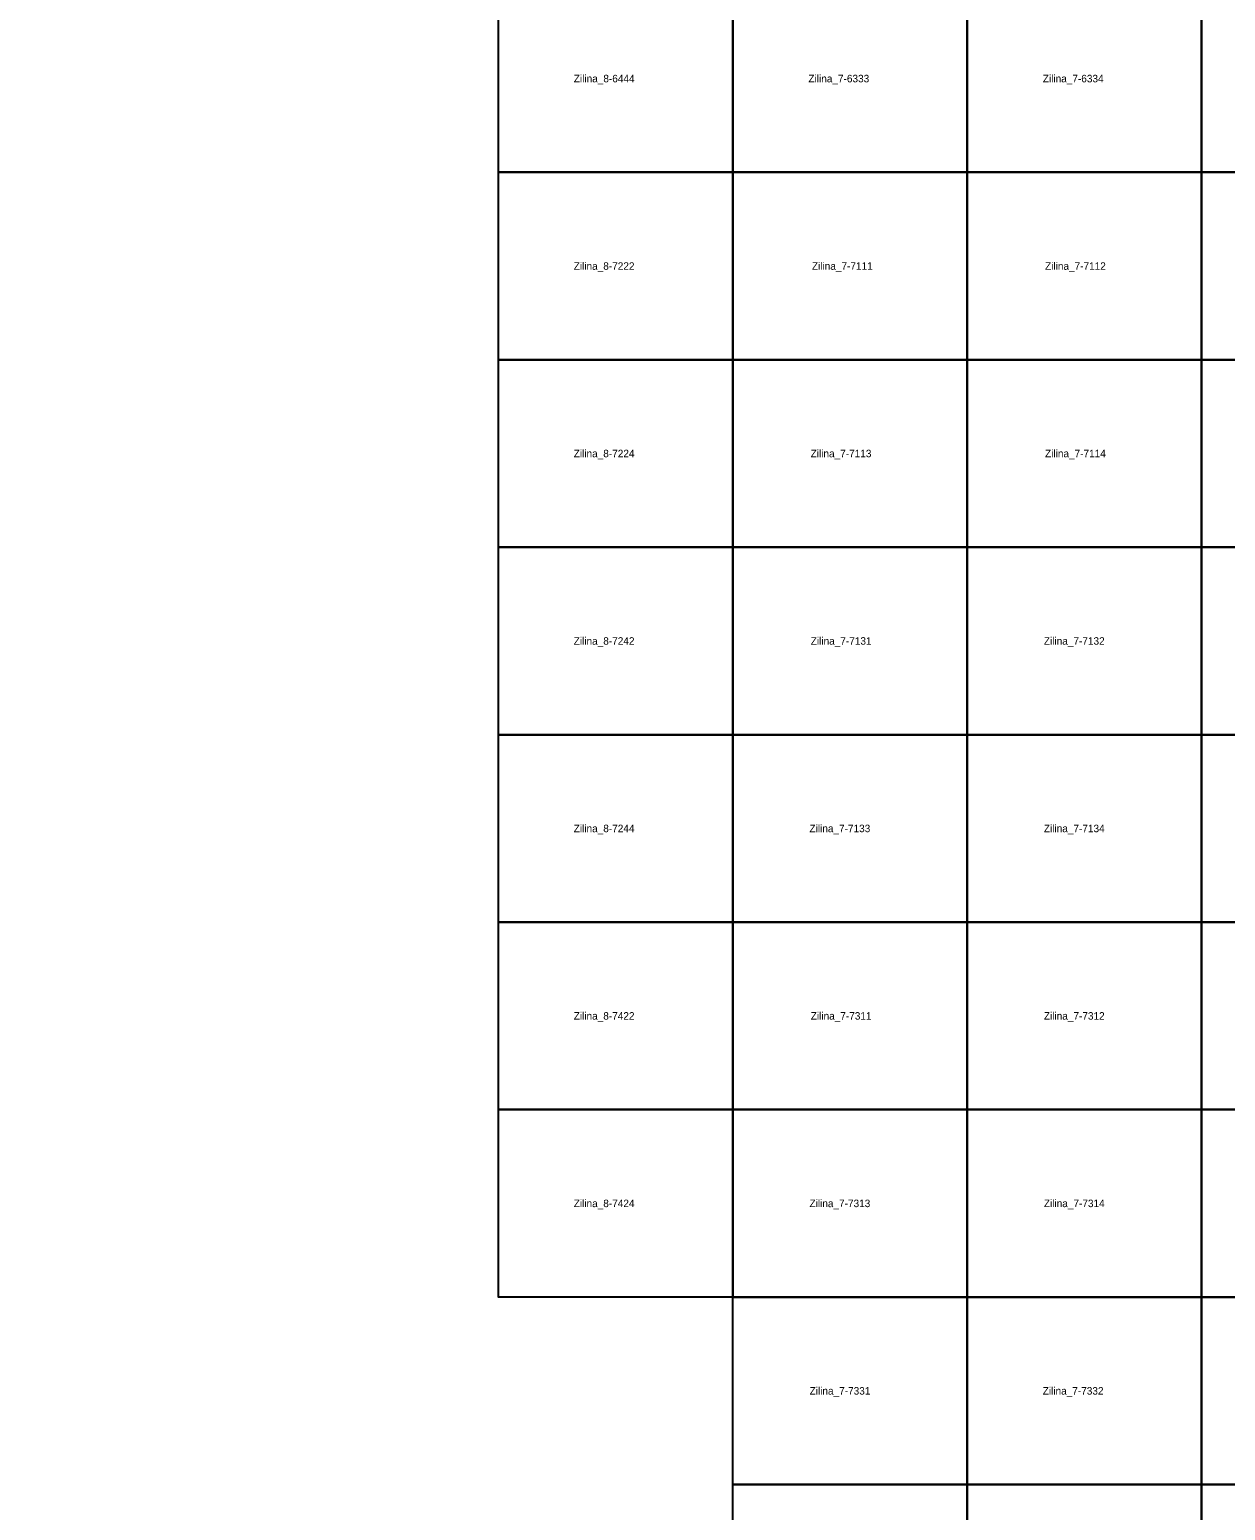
# Model space of a CAD drawing. Extents: x -445938 to -437812, y -1177250 to -1169500.
# Drawn here: x -445938 to -444343, y -1175784 to -1173810 of the extents above; entities that cross this region are included whole.
import ezdxf

# ---------------------------------------------------------------- set-up
doc = ezdxf.new("R2010")
doc.units = 0
for name, color, linetype in [('Vrstva 1', 7, 'Continuous'), ('Vrstva 4', 7, 'Continuous'), ('Vrstva 6', 7, 'Continuous')]:
    doc.layers.add(name, color=color, linetype=linetype)

msp = doc.modelspace()

# ---------------------------------------------------------------- linework, layer by layer
at = {"layer": 'Vrstva 1'}
msp.add_lwpolyline([(-440625, -1175500), (-441562.5, -1175500), (-441562.5, -1175000), (-442812.5, -1175000), (-442812.5, -1175750), (-443437.5, -1175750), (-443437.5, -1177250), (-445000, -1177250), (-445000, -1175500), (-445312.5, -1175500), (-445312.5, -1173750), (-445937.5, -1173750), (-445937.5, -1172250), (-445625, -1172250), (-445625, -1169500), (-444062.5, -1169500), (-444062.5, -1169750), (-441562.5, -1169750), (-441562.5, -1170000), (-440000, -1170000)], dxfattribs=at)
at = {"layer": 'Vrstva 4'}
for points in [[(-445000, -1173750), (-445000, -1174000), (-445312.5, -1174000), (-445312.5, -1173750)], [(-444687.5, -1173750), (-444687.5, -1174000), (-445000, -1174000), (-445000, -1173750)], [(-444375, -1173750), (-444375, -1174000), (-444687.5, -1174000), (-444687.5, -1173750)], [(-444062.5, -1173750), (-444062.5, -1174000), (-444375, -1174000), (-444375, -1173750)], [(-445000, -1174000), (-445000, -1174250), (-445312.5, -1174250), (-445312.5, -1174000)], [(-444687.5, -1174000), (-444687.5, -1174250), (-445000, -1174250), (-445000, -1174000)], [(-444375, -1174000), (-444375, -1174250), (-444687.5, -1174250), (-444687.5, -1174000)], [(-444062.5, -1174000), (-444062.5, -1174250), (-444375, -1174250), (-444375, -1174000)], [(-445000, -1174250), (-445000, -1174500), (-445312.5, -1174500), (-445312.5, -1174250)], [(-444687.5, -1174250), (-444687.5, -1174500), (-445000, -1174500), (-445000, -1174250)], [(-444375, -1174250), (-444375, -1174500), (-444687.5, -1174500), (-444687.5, -1174250)], [(-444062.5, -1174250), (-444062.5, -1174500), (-444375, -1174500), (-444375, -1174250)], [(-445000, -1174500), (-445000, -1174750), (-445312.5, -1174750), (-445312.5, -1174500)], [(-444687.5, -1174500), (-444687.5, -1174750), (-445000, -1174750), (-445000, -1174500)], [(-444375, -1174500), (-444375, -1174750), (-444687.5, -1174750), (-444687.5, -1174500)], [(-444062.5, -1174500), (-444062.5, -1174750), (-444375, -1174750), (-444375, -1174500)], [(-445000, -1174750), (-445000, -1175000), (-445312.5, -1175000), (-445312.5, -1174750)], [(-444687.5, -1174750), (-444687.5, -1175000), (-445000, -1175000), (-445000, -1174750)], [(-444375, -1174750), (-444375, -1175000), (-444687.5, -1175000), (-444687.5, -1174750)], [(-444062.5, -1174750), (-444062.5, -1175000), (-444375, -1175000), (-444375, -1174750)], [(-445000, -1175000), (-445000, -1175250), (-445312.5, -1175250), (-445312.5, -1175000)], [(-444687.5, -1175000), (-444687.5, -1175250), (-445000, -1175250), (-445000, -1175000)], [(-444375, -1175000), (-444375, -1175250), (-444687.5, -1175250), (-444687.5, -1175000)], [(-444062.5, -1175000), (-444062.5, -1175250), (-444375, -1175250), (-444375, -1175000)], [(-445000, -1175250), (-445000, -1175500), (-445312.5, -1175500), (-445312.5, -1175250)], [(-444687.5, -1175250), (-444687.5, -1175500), (-445000, -1175500), (-445000, -1175250)], [(-444375, -1175250), (-444375, -1175500), (-444687.5, -1175500), (-444687.5, -1175250)], [(-444062.5, -1175250), (-444062.5, -1175500), (-444375, -1175500), (-444375, -1175250)], [(-444687.5, -1175500), (-444687.5, -1175750), (-445000, -1175750), (-445000, -1175500)], [(-444375, -1175500), (-444375, -1175750), (-444687.5, -1175750), (-444687.5, -1175500)], [(-444062.5, -1175500), (-444062.5, -1175750), (-444375, -1175750), (-444375, -1175500)], [(-444687.5, -1175750), (-444687.5, -1176000), (-445000, -1176000), (-445000, -1175750)], [(-444375, -1175750), (-444375, -1176000), (-444687.5, -1176000), (-444687.5, -1175750)], [(-444062.5, -1175750), (-444062.5, -1176000), (-444375, -1176000), (-444375, -1175750)]]:
    msp.add_lwpolyline(points, close=True, dxfattribs=at)

# ---------------------------------------------------------------- texts
at = {"layer": 'Vrstva 6'}
for s, p in [('Zilina_8-6444', (-445211.954, -1173880)), ('Zilina_7-6333', (-444899.138, -1173880)), ('Zilina_7-6334', (-444586.638, -1173880)), ('Zilina_8-7222', (-445212.072, -1174130)), ('Zilina_7-7111', (-444894.494, -1174130)), ('Zilina_7-7112', (-444583.686, -1174130)), ('Zilina_8-7224', (-445212.072, -1174380)), ('Zilina_7-7113', (-444896.186, -1174380)), ('Zilina_7-7114', (-444583.686, -1174380)), ('Zilina_8-7242', (-445212.072, -1174630)), ('Zilina_7-7131', (-444896.028, -1174630)), ('Zilina_7-7132', (-444585.222, -1174630)), ('Zilina_8-7244', (-445212.072, -1174880)), ('Zilina_7-7133', (-444897.722, -1174880)), ('Zilina_7-7134', (-444585.222, -1174880)), ('Zilina_8-7422', (-445212.072, -1175130)), ('Zilina_7-7311', (-444896.028, -1175130)), ('Zilina_7-7312', (-444585.222, -1175130)), ('Zilina_8-7424', (-445212.072, -1175380)), ('Zilina_7-7313', (-444897.722, -1175380)), ('Zilina_7-7314', (-444585.222, -1175380)), ('Zilina_7-7331', (-444897.564, -1175630)), ('Zilina_7-7332', (-444586.756, -1175630))]:
    msp.add_text(s, height=10, dxfattribs=at).set_placement(p)

doc.saveas('drawing.dxf')
